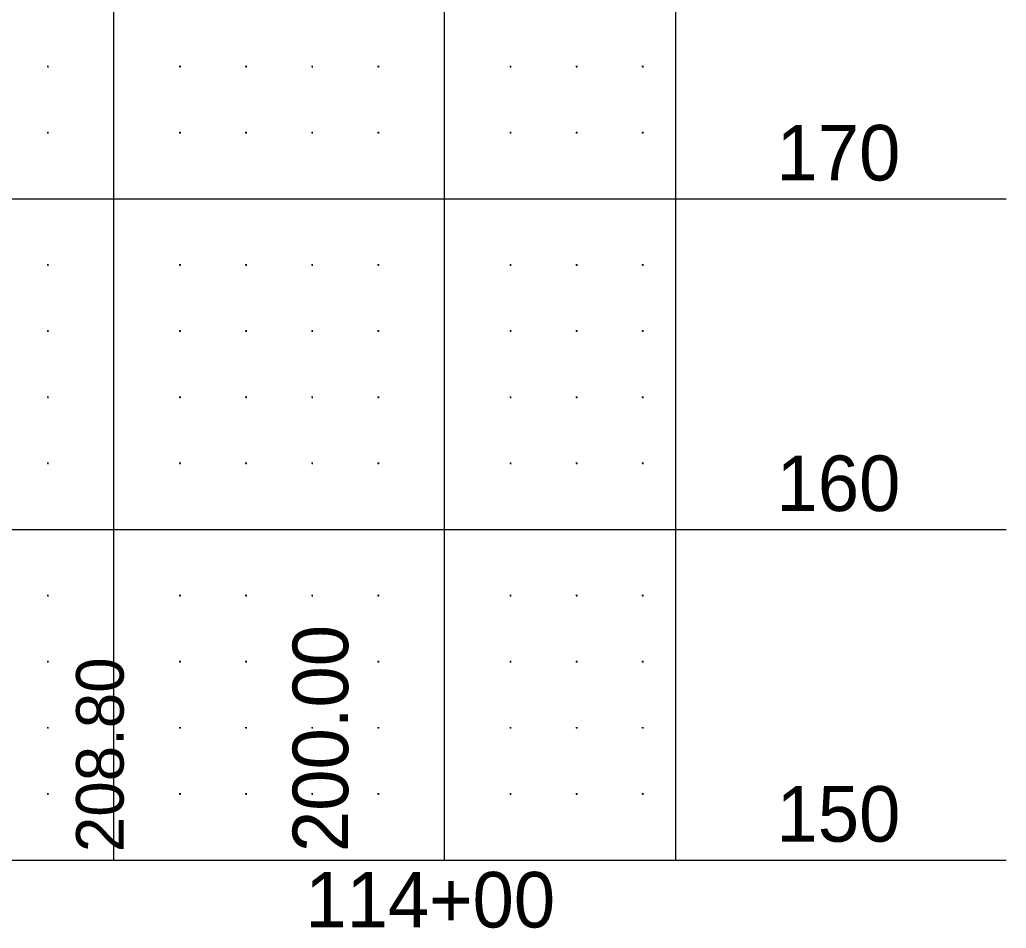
# Model space of a CAD drawing. Extents: x 471 to 2121, y 140 to 650.
# Drawn here: x 1971.8 to 2121.1, y 139.7 to 277.1 of the extents above; entities that cross this region are included whole.
import ezdxf

# ---------------------------------------------------------------- set-up
doc = ezdxf.new("R2010")
doc.units = 0
for name, color, linetype in [('DSN_DRFT_Border Grid', 7, 'Continuous'), ('DSN_RDWY_Prof Annotation', 7, 'Continuous'), ('EX_Profile Annotation', 7, 'Continuous')]:
    doc.layers.add(name, color=color, linetype=linetype)

msp = doc.modelspace()

# ---------------------------------------------------------------- linework, layer by layer
at = {"layer": 'DSN_DRFT_Border Grid'}
for p, q in [((1986.06, 150), (1986.06, 650)), ((1986.06, 150), (1986.06, 650)), ((2036.06, 150), (2036.06, 650)), ((2036.06, 150), (2036.06, 650)), ((2071.06, 150), (2071.06, 650)), ((2071.06, 150), (2071.06, 650)), ((1976.18, 270), (1975.94, 270)), ((1976.18, 270), (1975.94, 270)), ((1976.06, 270.12), (1976.06, 269.88)), ((1976.06, 270.12), (1976.06, 269.88)), ((1996.18, 270), (1995.94, 270)), ((1996.18, 270), (1995.94, 270)), ((1996.06, 270.12), (1996.06, 269.88)), ((1996.06, 270.12), (1996.06, 269.88)), ((2006.18, 270), (2005.94, 270)), ((2006.18, 270), (2005.94, 270)), ((2006.06, 270.12), (2006.06, 269.88)), ((2006.06, 270.12), (2006.06, 269.88)), ((2016.18, 270), (2015.94, 270)), ((2016.18, 270), (2015.94, 270)), ((2016.06, 270.12), (2016.06, 269.88)), ((2016.06, 270.12), (2016.06, 269.88)), ((2026.18, 270), (2025.94, 270)), ((2026.18, 270), (2025.94, 270)), ((2026.06, 270.12), (2026.06, 269.88)), ((2026.06, 270.12), (2026.06, 269.88)), ((2046.18, 270), (2045.94, 270)), ((2046.18, 270), (2045.94, 270)), ((2046.06, 270.12), (2046.06, 269.88)), ((2046.06, 270.12), (2046.06, 269.88)), ((2056.18, 270), (2055.94, 270)), ((2056.18, 270), (2055.94, 270)), ((2056.06, 270.12), (2056.06, 269.88)), ((2056.06, 270.12), (2056.06, 269.88)), ((2066.18, 270), (2065.94, 270)), ((2066.18, 270), (2065.94, 270)), ((2066.06, 270.12), (2066.06, 269.88)), ((2066.06, 270.12), (2066.06, 269.88)), ((1976.18, 260), (1975.94, 260)), ((1976.18, 260), (1975.94, 260)), ((1976.06, 260.12), (1976.06, 259.88)), ((1976.06, 260.12), (1976.06, 259.88)), ((1996.18, 260), (1995.94, 260)), ((1996.18, 260), (1995.94, 260)), ((1996.06, 260.12), (1996.06, 259.88)), ((1996.06, 260.12), (1996.06, 259.88)), ((2006.18, 260), (2005.94, 260)), ((2006.18, 260), (2005.94, 260)), ((2006.06, 260.12), (2006.06, 259.88)), ((2006.06, 260.12), (2006.06, 259.88)), ((2016.18, 260), (2015.94, 260)), ((2016.18, 260), (2015.94, 260)), ((2016.06, 260.12), (2016.06, 259.88)), ((2016.06, 260.12), (2016.06, 259.88)), ((2026.18, 260), (2025.94, 260)), ((2026.18, 260), (2025.94, 260)), ((2026.06, 260.12), (2026.06, 259.88)), ((2026.06, 260.12), (2026.06, 259.88)), ((2046.18, 260), (2045.94, 260)), ((2046.18, 260), (2045.94, 260)), ((2046.06, 260.12), (2046.06, 259.88)), ((2046.06, 260.12), (2046.06, 259.88)), ((2056.18, 260), (2055.94, 260)), ((2056.18, 260), (2055.94, 260)), ((2056.06, 260.12), (2056.06, 259.88)), ((2056.06, 260.12), (2056.06, 259.88)), ((2066.18, 260), (2065.94, 260)), ((2066.18, 260), (2065.94, 260)), ((2066.06, 260.12), (2066.06, 259.88)), ((2066.06, 260.12), (2066.06, 259.88)), ((521.06, 250), (2071.06, 250)), ((521.06, 250), (2071.06, 250)), ((2071.06, 250), (2121.06, 250)), ((1976.18, 240), (1975.94, 240)), ((1976.18, 240), (1975.94, 240)), ((1976.06, 240.12), (1976.06, 239.88)), ((1976.06, 240.12), (1976.06, 239.88)), ((1996.18, 240), (1995.94, 240)), ((1996.18, 240), (1995.94, 240)), ((1996.06, 240.12), (1996.06, 239.88)), ((1996.06, 240.12), (1996.06, 239.88)), ((2006.18, 240), (2005.94, 240)), ((2006.18, 240), (2005.94, 240)), ((2006.06, 240.12), (2006.06, 239.88)), ((2006.06, 240.12), (2006.06, 239.88)), ((2016.18, 240), (2015.94, 240)), ((2016.18, 240), (2015.94, 240)), ((2016.06, 240.12), (2016.06, 239.88)), ((2016.06, 240.12), (2016.06, 239.88)), ((2026.18, 240), (2025.94, 240)), ((2026.18, 240), (2025.94, 240)), ((2026.06, 240.12), (2026.06, 239.88)), ((2026.06, 240.12), (2026.06, 239.88)), ((2046.18, 240), (2045.94, 240)), ((2046.18, 240), (2045.94, 240)), ((2046.06, 240.12), (2046.06, 239.88)), ((2046.06, 240.12), (2046.06, 239.88)), ((2056.18, 240), (2055.94, 240)), ((2056.18, 240), (2055.94, 240)), ((2056.06, 240.12), (2056.06, 239.88)), ((2056.06, 240.12), (2056.06, 239.88)), ((2066.18, 240), (2065.94, 240)), ((2066.18, 240), (2065.94, 240)), ((2066.06, 240.12), (2066.06, 239.88)), ((2066.06, 240.12), (2066.06, 239.88)), ((1976.18, 230), (1975.94, 230)), ((1976.18, 230), (1975.94, 230)), ((1976.06, 230.12), (1976.06, 229.88)), ((1976.06, 230.12), (1976.06, 229.88)), ((1996.18, 230), (1995.94, 230)), ((1996.18, 230), (1995.94, 230)), ((1996.06, 230.12), (1996.06, 229.88)), ((1996.06, 230.12), (1996.06, 229.88)), ((2006.18, 230), (2005.94, 230)), ((2006.18, 230), (2005.94, 230)), ((2006.06, 230.12), (2006.06, 229.88)), ((2006.06, 230.12), (2006.06, 229.88)), ((2016.18, 230), (2015.94, 230)), ((2016.18, 230), (2015.94, 230)), ((2016.06, 230.12), (2016.06, 229.88)), ((2016.06, 230.12), (2016.06, 229.88)), ((2026.18, 230), (2025.94, 230)), ((2026.18, 230), (2025.94, 230)), ((2026.06, 230.12), (2026.06, 229.88)), ((2026.06, 230.12), (2026.06, 229.88)), ((2046.18, 230), (2045.94, 230)), ((2046.18, 230), (2045.94, 230)), ((2046.06, 230.12), (2046.06, 229.88)), ((2046.06, 230.12), (2046.06, 229.88)), ((2056.18, 230), (2055.94, 230)), ((2056.18, 230), (2055.94, 230)), ((2056.06, 230.12), (2056.06, 229.88)), ((2056.06, 230.12), (2056.06, 229.88)), ((2066.18, 230), (2065.94, 230)), ((2066.18, 230), (2065.94, 230)), ((2066.06, 230.12), (2066.06, 229.88)), ((2066.06, 230.12), (2066.06, 229.88)), ((1976.18, 220), (1975.94, 220)), ((1976.18, 220), (1975.94, 220)), ((1976.06, 220.12), (1976.06, 219.88)), ((1976.06, 220.12), (1976.06, 219.88)), ((1996.18, 220), (1995.94, 220)), ((1996.18, 220), (1995.94, 220)), ((1996.06, 220.12), (1996.06, 219.88)), ((1996.06, 220.12), (1996.06, 219.88)), ((2006.18, 220), (2005.94, 220)), ((2006.18, 220), (2005.94, 220)), ((2006.06, 220.12), (2006.06, 219.88)), ((2006.06, 220.12), (2006.06, 219.88)), ((2016.18, 220), (2015.94, 220)), ((2016.18, 220), (2015.94, 220)), ((2016.06, 220.12), (2016.06, 219.88)), ((2016.06, 220.12), (2016.06, 219.88)), ((2026.18, 220), (2025.94, 220)), ((2026.18, 220), (2025.94, 220)), ((2026.06, 220.12), (2026.06, 219.88)), ((2026.06, 220.12), (2026.06, 219.88)), ((2046.18, 220), (2045.94, 220)), ((2046.18, 220), (2045.94, 220)), ((2046.06, 220.12), (2046.06, 219.88)), ((2046.06, 220.12), (2046.06, 219.88)), ((2056.18, 220), (2055.94, 220)), ((2056.18, 220), (2055.94, 220)), ((2056.06, 220.12), (2056.06, 219.88)), ((2056.06, 220.12), (2056.06, 219.88)), ((2066.18, 220), (2065.94, 220)), ((2066.18, 220), (2065.94, 220)), ((2066.06, 220.12), (2066.06, 219.88)), ((2066.06, 220.12), (2066.06, 219.88)), ((1976.18, 210), (1975.94, 210)), ((1976.18, 210), (1975.94, 210)), ((1976.06, 210.12), (1976.06, 209.88)), ((1976.06, 210.12), (1976.06, 209.88)), ((1996.18, 210), (1995.94, 210)), ((1996.18, 210), (1995.94, 210)), ((1996.06, 210.12), (1996.06, 209.88)), ((1996.06, 210.12), (1996.06, 209.88)), ((2006.18, 210), (2005.94, 210)), ((2006.18, 210), (2005.94, 210)), ((2006.06, 210.12), (2006.06, 209.88)), ((2006.06, 210.12), (2006.06, 209.88)), ((2016.18, 210), (2015.94, 210)), ((2016.18, 210), (2015.94, 210)), ((2016.06, 210.12), (2016.06, 209.88)), ((2016.06, 210.12), (2016.06, 209.88)), ((2026.18, 210), (2025.94, 210)), ((2026.18, 210), (2025.94, 210)), ((2026.06, 210.12), (2026.06, 209.88)), ((2026.06, 210.12), (2026.06, 209.88)), ((2046.18, 210), (2045.94, 210)), ((2046.18, 210), (2045.94, 210)), ((2046.06, 210.12), (2046.06, 209.88)), ((2046.06, 210.12), (2046.06, 209.88)), ((2056.18, 210), (2055.94, 210)), ((2056.18, 210), (2055.94, 210)), ((2056.06, 210.12), (2056.06, 209.88)), ((2056.06, 210.12), (2056.06, 209.88)), ((2066.18, 210), (2065.94, 210)), ((2066.18, 210), (2065.94, 210)), ((2066.06, 210.12), (2066.06, 209.88)), ((2066.06, 210.12), (2066.06, 209.88)), ((521.06, 200), (2071.06, 200)), ((521.06, 200), (2071.06, 200)), ((2071.06, 200), (2121.06, 200)), ((1976.18, 190), (1975.94, 190)), ((1976.18, 190), (1975.94, 190)), ((1976.06, 190.12), (1976.06, 189.88)), ((1976.06, 190.12), (1976.06, 189.88)), ((1996.18, 190), (1995.94, 190)), ((1996.18, 190), (1995.94, 190)), ((1996.06, 190.12), (1996.06, 189.88)), ((1996.06, 190.12), (1996.06, 189.88)), ((2006.18, 190), (2005.94, 190)), ((2006.18, 190), (2005.94, 190)), ((2006.06, 190.12), (2006.06, 189.88)), ((2006.06, 190.12), (2006.06, 189.88)), ((2016.18, 190), (2015.94, 190)), ((2016.18, 190), (2015.94, 190)), ((2016.06, 190.12), (2016.06, 189.88)), ((2016.06, 190.12), (2016.06, 189.88)), ((2026.18, 190), (2025.94, 190)), ((2026.18, 190), (2025.94, 190)), ((2026.06, 190.12), (2026.06, 189.88)), ((2026.06, 190.12), (2026.06, 189.88)), ((2046.18, 190), (2045.94, 190)), ((2046.18, 190), (2045.94, 190)), ((2046.06, 190.12), (2046.06, 189.88)), ((2046.06, 190.12), (2046.06, 189.88)), ((2056.18, 190), (2055.94, 190)), ((2056.18, 190), (2055.94, 190)), ((2056.06, 190.12), (2056.06, 189.88)), ((2056.06, 190.12), (2056.06, 189.88)), ((2066.18, 190), (2065.94, 190)), ((2066.18, 190), (2065.94, 190)), ((2066.06, 190.12), (2066.06, 189.88)), ((2066.06, 190.12), (2066.06, 189.88)), ((1976.18, 180), (1975.94, 180)), ((1976.18, 180), (1975.94, 180)), ((1976.06, 180.12), (1976.06, 179.88)), ((1976.06, 180.12), (1976.06, 179.88)), ((1996.18, 180), (1995.94, 180)), ((1996.18, 180), (1995.94, 180)), ((1996.06, 180.12), (1996.06, 179.88)), ((1996.06, 180.12), (1996.06, 179.88)), ((2006.18, 180), (2005.94, 180)), ((2006.18, 180), (2005.94, 180)), ((2006.06, 180.12), (2006.06, 179.88)), ((2006.06, 180.12), (2006.06, 179.88)), ((2016.18, 180), (2015.94, 180)), ((2016.18, 180), (2015.94, 180)), ((2016.06, 180.12), (2016.06, 179.88)), ((2016.06, 180.12), (2016.06, 179.88)), ((2026.18, 180), (2025.94, 180)), ((2026.18, 180), (2025.94, 180)), ((2026.06, 180.12), (2026.06, 179.88)), ((2026.06, 180.12), (2026.06, 179.88)), ((2046.18, 180), (2045.94, 180)), ((2046.18, 180), (2045.94, 180)), ((2046.06, 180.12), (2046.06, 179.88)), ((2046.06, 180.12), (2046.06, 179.88)), ((2056.18, 180), (2055.94, 180)), ((2056.18, 180), (2055.94, 180)), ((2056.06, 180.12), (2056.06, 179.88)), ((2056.06, 180.12), (2056.06, 179.88)), ((2066.18, 180), (2065.94, 180)), ((2066.18, 180), (2065.94, 180)), ((2066.06, 180.12), (2066.06, 179.88)), ((2066.06, 180.12), (2066.06, 179.88)), ((1976.18, 170), (1975.94, 170)), ((1976.18, 170), (1975.94, 170)), ((1976.06, 170.12), (1976.06, 169.88)), ((1976.06, 170.12), (1976.06, 169.88)), ((1996.18, 170), (1995.94, 170)), ((1996.18, 170), (1995.94, 170)), ((1996.06, 170.12), (1996.06, 169.88)), ((1996.06, 170.12), (1996.06, 169.88)), ((2006.18, 170), (2005.94, 170)), ((2006.18, 170), (2005.94, 170)), ((2006.06, 170.12), (2006.06, 169.88)), ((2006.06, 170.12), (2006.06, 169.88)), ((2016.18, 170), (2015.94, 170)), ((2016.18, 170), (2015.94, 170)), ((2016.06, 170.12), (2016.06, 169.88)), ((2016.06, 170.12), (2016.06, 169.88)), ((2026.18, 170), (2025.94, 170)), ((2026.18, 170), (2025.94, 170)), ((2026.06, 170.12), (2026.06, 169.88)), ((2026.06, 170.12), (2026.06, 169.88)), ((2046.18, 170), (2045.94, 170)), ((2046.18, 170), (2045.94, 170)), ((2046.06, 170.12), (2046.06, 169.88)), ((2046.06, 170.12), (2046.06, 169.88)), ((2056.18, 170), (2055.94, 170)), ((2056.18, 170), (2055.94, 170)), ((2056.06, 170.12), (2056.06, 169.88)), ((2056.06, 170.12), (2056.06, 169.88)), ((2066.18, 170), (2065.94, 170)), ((2066.18, 170), (2065.94, 170)), ((2066.06, 170.12), (2066.06, 169.88)), ((2066.06, 170.12), (2066.06, 169.88)), ((1976.18, 160), (1975.94, 160)), ((1976.18, 160), (1975.94, 160)), ((1976.06, 160.12), (1976.06, 159.88)), ((1976.06, 160.12), (1976.06, 159.88)), ((1996.18, 160), (1995.94, 160)), ((1996.18, 160), (1995.94, 160)), ((1996.06, 160.12), (1996.06, 159.88)), ((1996.06, 160.12), (1996.06, 159.88)), ((2006.18, 160), (2005.94, 160)), ((2006.18, 160), (2005.94, 160)), ((2006.06, 160.12), (2006.06, 159.88)), ((2006.06, 160.12), (2006.06, 159.88)), ((2016.18, 160), (2015.94, 160)), ((2016.18, 160), (2015.94, 160)), ((2016.06, 160.12), (2016.06, 159.88)), ((2016.06, 160.12), (2016.06, 159.88)), ((2026.18, 160), (2025.94, 160)), ((2026.18, 160), (2025.94, 160)), ((2026.06, 160.12), (2026.06, 159.88)), ((2026.06, 160.12), (2026.06, 159.88)), ((2046.18, 160), (2045.94, 160)), ((2046.18, 160), (2045.94, 160)), ((2046.06, 160.12), (2046.06, 159.88)), ((2046.06, 160.12), (2046.06, 159.88)), ((2056.18, 160), (2055.94, 160)), ((2056.18, 160), (2055.94, 160)), ((2056.06, 160.12), (2056.06, 159.88)), ((2056.06, 160.12), (2056.06, 159.88)), ((2066.18, 160), (2065.94, 160)), ((2066.18, 160), (2065.94, 160)), ((2066.06, 160.12), (2066.06, 159.88)), ((2066.06, 160.12), (2066.06, 159.88)), ((521.06, 150), (2071.06, 150)), ((521.06, 150), (2071.06, 150)), ((2071.06, 150), (2121.06, 150))]:
    msp.add_line(p, q, dxfattribs=at)

# ---------------------------------------------------------------- texts
at = {"layer": 'DSN_RDWY_Prof Annotation'}
for s, p in [('170', (2086.3, 252.78)), ('170', (2086.3, 252.78)), ('160', (2086.3, 202.78)), ('160', (2086.3, 202.78)), ('150', (2086.3, 152.78)), ('114+00', (2015.02, 139.8)), ('114+00', (2015.02, 139.8))]:
    msp.add_text(s, height=8.4, dxfattribs=at).set_placement(p)
msp.add_text('200.00', height=8.4, rotation=90, dxfattribs=at).set_placement((2021.5, 151.2))
at = {"layer": 'EX_Profile Annotation'}
msp.add_text('208.80', height=7.2, rotation=90, dxfattribs=at).set_placement((1987.54, 151.2))

doc.saveas('drawing.dxf')
